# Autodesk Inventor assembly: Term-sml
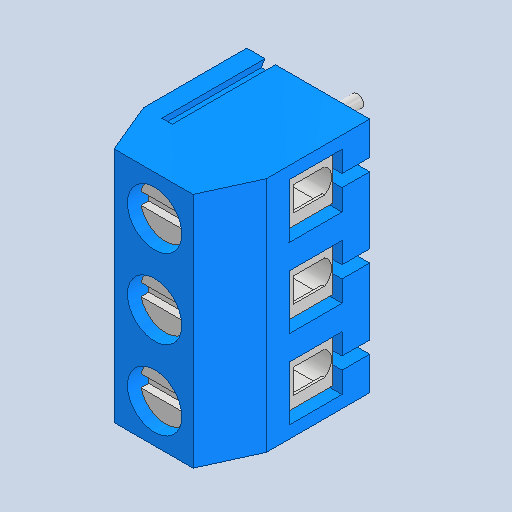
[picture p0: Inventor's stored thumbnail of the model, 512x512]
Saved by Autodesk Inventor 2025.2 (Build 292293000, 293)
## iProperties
Created: 2025-04
Part Number: Term-sml
Description: PART--DESC
Document SubType Name: Assembly
Designer: BennF
Author: BennF
Revision Number: NONE
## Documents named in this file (3)
- C:\Users\BennF\Nextcloud\Benutzer\CNC JarBeRi\existing parts\Electronics\RepRap A4988 Shied (USE WITHOUT ARDUINO)\reprap-a4988-1.snapshot.1\RepRap\RepRap\Term-sml.iam
- C:\Users\BennF\Nextcloud\Benutzer\CNC JarBeRi\existing parts\Electronics\RepRap A4988 Shied (USE WITHOUT ARDUINO)\reprap-a4988-1.snapshot.1\RepRap\RepRap\Term-sml Geometry.ipt
- C:\Users\BennF\Nextcloud\Benutzer\CNC JarBeRi\existing parts\Electronics\RepRap A4988 Shied (USE WITHOUT ARDUINO)\reprap-a4988-1.snapshot.1\RepRap\RepRap\pins.ipt
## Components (2 placed, 2 different names)
1. Term-sml Geometry
2. pins
